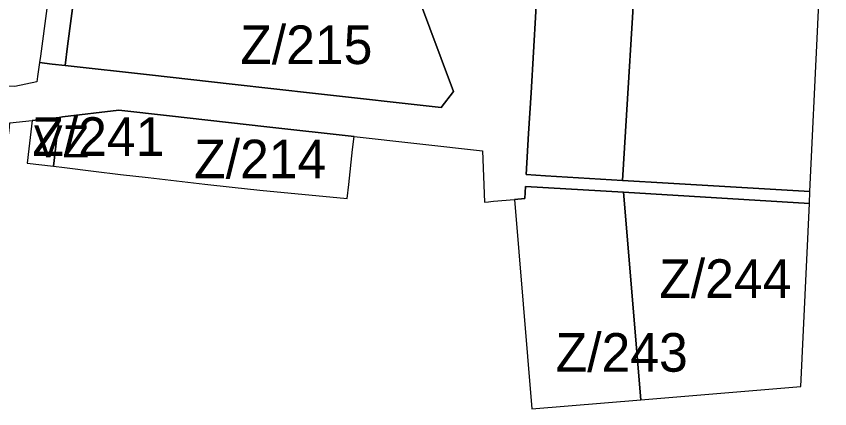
# Model space of a CAD drawing. Extents: x -521939 to -518034, y -1194984 to -1189555.
# Drawn here: x -519479.8 to -519227.4, y -1191543.3 to -1191421.3 of the extents above; entities that cross this region are included whole.
import ezdxf

# ---------------------------------------------------------------- set-up
doc = ezdxf.new("R2010")
doc.units = 0
for name, color, linetype in [('95420023', 7, 'Continuous'), ('96202223', 7, 'Continuous'), ('96202323', 7, 'Continuous')]:
    doc.layers.add(name, color=color, linetype=linetype)

msp = doc.modelspace()

# ---------------------------------------------------------------- linework, layer by layer
at = {"layer": '95420023'}
for points in [[(-519443.51, -1191215.75), (-519445.75, -1191232.74), (-519448.07, -1191250.27), (-519450.34, -1191267.46), (-519451.46, -1191275.9), (-519452.43, -1191283.22), (-519454.38, -1191298), (-519457.39, -1191320.76), (-519458.94, -1191332.49), (-519461, -1191348.01), (-519463.15, -1191364.31), (-519465.11, -1191379.15), (-519467.09, -1191394.09), (-519468.15, -1191402.09), (-519468.71, -1191406.36), (-519470.37, -1191418.91), (-519472.32, -1191433.7), (-519472.58, -1191435.69)], [(-519313.69, -1191339.37), (-519315.32, -1191366.47), (-519316.93, -1191393.15), (-519317.5, -1191402.75), (-519318.53, -1191419.83), (-519320.06, -1191445.13), (-519320.82, -1191457.76)], [(-519233.5, -1191475.79), (-519231.17, -1191426.05), (-519228.55, -1191370.34), (-519227.35, -1191344.57), (-519270.52, -1191341.97)], [(-519344.11, -1191444.69), (-519355.34, -1191414.63), (-519369.81, -1191375.88)], [(-519286.98, -1191394.95), (-519288.59, -1191421.63), (-519290.11, -1191446.93)], [(-519288.59, -1191421.63), (-519286.98, -1191394.95)], [(-519320.82, -1191457.76), (-519320.06, -1191445.13), (-519318.53, -1191419.83), (-519317.5, -1191402.75)], [(-519410, -1191417.54), (-519435.74, -1191414.66), (-519461.41, -1191411.78), (-519463.91, -1191430.62)], [(-519463.91, -1191430.62), (-519461.41, -1191411.78)], [(-519355.34, -1191414.63), (-519344.11, -1191444.69), (-519347.98, -1191449.64), (-519386.94, -1191445.28), (-519412.78, -1191442.38)], [(-519290.11, -1191446.93), (-519288.59, -1191421.63)], [(-519463.91, -1191430.62), (-519464.69, -1191436.57)], [(-519464.69, -1191436.57), (-519463.91, -1191430.62)], [(-519468.64, -1191436.13), (-519472.58, -1191435.69), (-519472.77, -1191437.09), (-519473.18, -1191440.03), (-519473.41, -1191441.72), (-519480.3, -1191443.11), (-519533.77, -1191442.8), (-519544.94, -1191442.33), (-519556.21, -1191444.23), (-519556.39, -1191445.91), (-519562.18, -1191445.17), (-519566.72, -1191444.78), (-519566.62, -1191443.98), (-519575.16, -1191444.67), (-519576.66, -1191452.79), (-519577.4, -1191456.82), (-519577.64, -1191459.18), (-519577.51, -1191465.05), (-519544.61, -1191464.84), (-519540.95, -1191464.89)], [(-519472.58, -1191435.69), (-519468.64, -1191436.13), (-519464.69, -1191436.57)], [(-519464.69, -1191436.57), (-519468.64, -1191436.13)], [(-519464.69, -1191436.57), (-519438.52, -1191439.5), (-519412.78, -1191442.38), (-519386.94, -1191445.28)], [(-519412.78, -1191442.38), (-519438.52, -1191439.5), (-519464.69, -1191436.57)], [(-519386.94, -1191445.28), (-519347.98, -1191449.64), (-519344.11, -1191444.69)], [(-519290.11, -1191446.93), (-519291.64, -1191472.29)], [(-519291.64, -1191472.29), (-519290.11, -1191446.93)], [(-519466.53, -1191452.71), (-519465.48, -1191452.58), (-519448.03, -1191450.51)], [(-519432.28, -1191452.28), (-519448.03, -1191450.51), (-519465.48, -1191452.58)], [(-519448.03, -1191450.51), (-519432.28, -1191452.28)], [(-519483.25, -1191465.69), (-519481.98, -1191456.8), (-519481.78, -1191454.44), (-519474.91, -1191453.7)], [(-519474.91, -1191453.7), (-519475.89, -1191462.49), (-519476.39, -1191466.96), (-519468.24, -1191467.91)], [(-519466.53, -1191452.71), (-519474.91, -1191453.7)], [(-519474.91, -1191453.7), (-519466.53, -1191452.71)], [(-519466.53, -1191452.71), (-519467.73, -1191463.4)], [(-519467.73, -1191463.4), (-519466.53, -1191452.71)], [(-519465.48, -1191452.58), (-519466.53, -1191452.71)], [(-519374.98, -1191458.69), (-519402.01, -1191455.67), (-519432.28, -1191452.28)], [(-519432.28, -1191452.28), (-519402.01, -1191455.67)], [(-519402.01, -1191455.67), (-519374.98, -1191458.69)], [(-519468.24, -1191467.91), (-519464.87, -1191468.3), (-519455.9, -1191469.38), (-519447.43, -1191470.43), (-519438.84, -1191471.35), (-519430.1, -1191472.39), (-519421.34, -1191473.46), (-519412.86, -1191474.37), (-519404.22, -1191475.38), (-519377.14, -1191477.95), (-519376.65, -1191473.6), (-519375.43, -1191462.67), (-519374.98, -1191458.69)], [(-519374.98, -1191458.69), (-519335.08, -1191463.16), (-519334.48, -1191479.02), (-519333.28, -1191478.93), (-519332.56, -1191478.87), (-519331.7, -1191478.8), (-519325.22, -1191478.24)], [(-519320.82, -1191457.76), (-519321.58, -1191470.48)], [(-519321.58, -1191470.48), (-519320.82, -1191457.76)], [(-519467.73, -1191463.4), (-519468.24, -1191467.91)], [(-519468.24, -1191467.91), (-519467.73, -1191463.4)], [(-519321.58, -1191470.48), (-519315.59, -1191470.85)], [(-519315.59, -1191470.85), (-519321.58, -1191470.48)], [(-519315.59, -1191470.85), (-519291.64, -1191472.29)], [(-519291.64, -1191472.29), (-519315.59, -1191470.85)], [(-519322.03, -1191477.97), (-519321.8, -1191474.15), (-519291.33, -1191476), (-519233.67, -1191479.5), (-519233.5, -1191475.79), (-519277.54, -1191473.14), (-519291.64, -1191472.29)], [(-519291.64, -1191472.29), (-519277.54, -1191473.14)], [(-519277.54, -1191473.14), (-519233.5, -1191475.79)], [(-519321.8, -1191474.15), (-519322.03, -1191477.97)], [(-519291.33, -1191476), (-519321.8, -1191474.15)], [(-519285.93, -1191540.47), (-519291.33, -1191476)], [(-519233.67, -1191479.5), (-519291.33, -1191476)], [(-519291.33, -1191476), (-519285.93, -1191540.47)], [(-519322.03, -1191477.97), (-519325.22, -1191478.24), (-519319.78, -1191543.27), (-519285.93, -1191540.47)], [(-519325.22, -1191478.24), (-519322.03, -1191477.97)], [(-519285.93, -1191540.47), (-519236.33, -1191536.36), (-519233.67, -1191479.5)]]:
    msp.add_lwpolyline(points, dxfattribs=at)
at = {"layer": '96202223'}
for points in [[(-519443.51, -1191215.75), (-519445.75, -1191232.74), (-519448.07, -1191250.27), (-519450.34, -1191267.46), (-519451.46, -1191275.9), (-519452.43, -1191283.22), (-519454.38, -1191298), (-519457.39, -1191320.76), (-519458.94, -1191332.49), (-519461, -1191348.01), (-519463.15, -1191364.31), (-519465.11, -1191379.15), (-519467.09, -1191394.09), (-519468.15, -1191402.09), (-519468.71, -1191406.36), (-519470.37, -1191418.91), (-519472.32, -1191433.7), (-519472.58, -1191435.69)], [(-519463.91, -1191430.62), (-519461.41, -1191411.78)], [(-519464.69, -1191436.57), (-519463.91, -1191430.62)], [(-519472.58, -1191435.69), (-519468.64, -1191436.13)], [(-519468.64, -1191436.13), (-519464.69, -1191436.57)], [(-519474.91, -1191453.7), (-519475.89, -1191462.49), (-519476.39, -1191466.96), (-519468.24, -1191467.91)], [(-519466.53, -1191452.71), (-519474.91, -1191453.7)], [(-519467.73, -1191463.4), (-519466.53, -1191452.71)], [(-519468.24, -1191467.91), (-519467.73, -1191463.4)]]:
    msp.add_lwpolyline(points, dxfattribs=at)
at = {"layer": '96202323'}
for points in [[(-519355.34, -1191414.63), (-519344.11, -1191444.69)], [(-519320.82, -1191457.76), (-519320.06, -1191445.13), (-519318.53, -1191419.83)], [(-519468.64, -1191436.13), (-519472.58, -1191435.69), (-519472.77, -1191437.09), (-519473.18, -1191440.03), (-519473.41, -1191441.72), (-519480.3, -1191443.11), (-519533.77, -1191442.8), (-519544.94, -1191442.33), (-519556.21, -1191444.23), (-519556.39, -1191445.91), (-519562.18, -1191445.17), (-519566.72, -1191444.78), (-519566.62, -1191443.98), (-519575.16, -1191444.67), (-519576.66, -1191452.79), (-519577.4, -1191456.82), (-519577.64, -1191459.18), (-519577.51, -1191465.05), (-519544.61, -1191464.84), (-519540.95, -1191464.89)], [(-519464.69, -1191436.57), (-519468.64, -1191436.13)], [(-519412.78, -1191442.38), (-519438.52, -1191439.5), (-519464.69, -1191436.57)], [(-519347.98, -1191449.64), (-519386.94, -1191445.28), (-519412.78, -1191442.38)], [(-519344.11, -1191444.69), (-519347.98, -1191449.64)], [(-519465.48, -1191452.58), (-519448.03, -1191450.51), (-519432.28, -1191452.28)], [(-519483.25, -1191465.69), (-519481.98, -1191456.8), (-519481.78, -1191454.44), (-519474.91, -1191453.7)], [(-519474.91, -1191453.7), (-519466.53, -1191452.71)], [(-519466.53, -1191452.71), (-519465.48, -1191452.58)], [(-519432.28, -1191452.28), (-519402.01, -1191455.67)], [(-519402.01, -1191455.67), (-519374.98, -1191458.69)], [(-519374.98, -1191458.69), (-519335.08, -1191463.16), (-519334.48, -1191479.02), (-519333.28, -1191478.93), (-519332.56, -1191478.87), (-519331.7, -1191478.8), (-519325.22, -1191478.24)], [(-519321.58, -1191470.48), (-519320.82, -1191457.76)], [(-519315.59, -1191470.85), (-519321.58, -1191470.48)], [(-519291.64, -1191472.29), (-519315.59, -1191470.85)], [(-519277.54, -1191473.14), (-519291.64, -1191472.29)], [(-519233.5, -1191475.79), (-519277.54, -1191473.14)], [(-519322.03, -1191477.97), (-519321.8, -1191474.15), (-519291.33, -1191476)], [(-519291.33, -1191476), (-519233.67, -1191479.5)], [(-519233.67, -1191479.5), (-519233.5, -1191475.79)], [(-519325.22, -1191478.24), (-519322.03, -1191477.97)]]:
    msp.add_lwpolyline(points, dxfattribs=at)

# ---------------------------------------------------------------- texts
at = {"layer": '95420023'}
for s, rotation, p in [('Z/215', 360, (-519410.32, -1191436.15)), ('Z/241', 0, (-519474.87, -1191464.68)), ('Z/214', 360, (-519424.63, -1191471.66)), ('Z/244', 0, (-519280.27, -1191508.82)), ('Z/243', 0, (-519312.43, -1191531.76))]:
    msp.add_text(s, height=12, rotation=rotation, dxfattribs=at).set_placement(p)
at = {"layer": '96202223'}
msp.add_text('VZ', height=10, rotation=360, dxfattribs=at).set_placement((-519474.34, -1191465.17))

doc.saveas('drawing.dxf')
